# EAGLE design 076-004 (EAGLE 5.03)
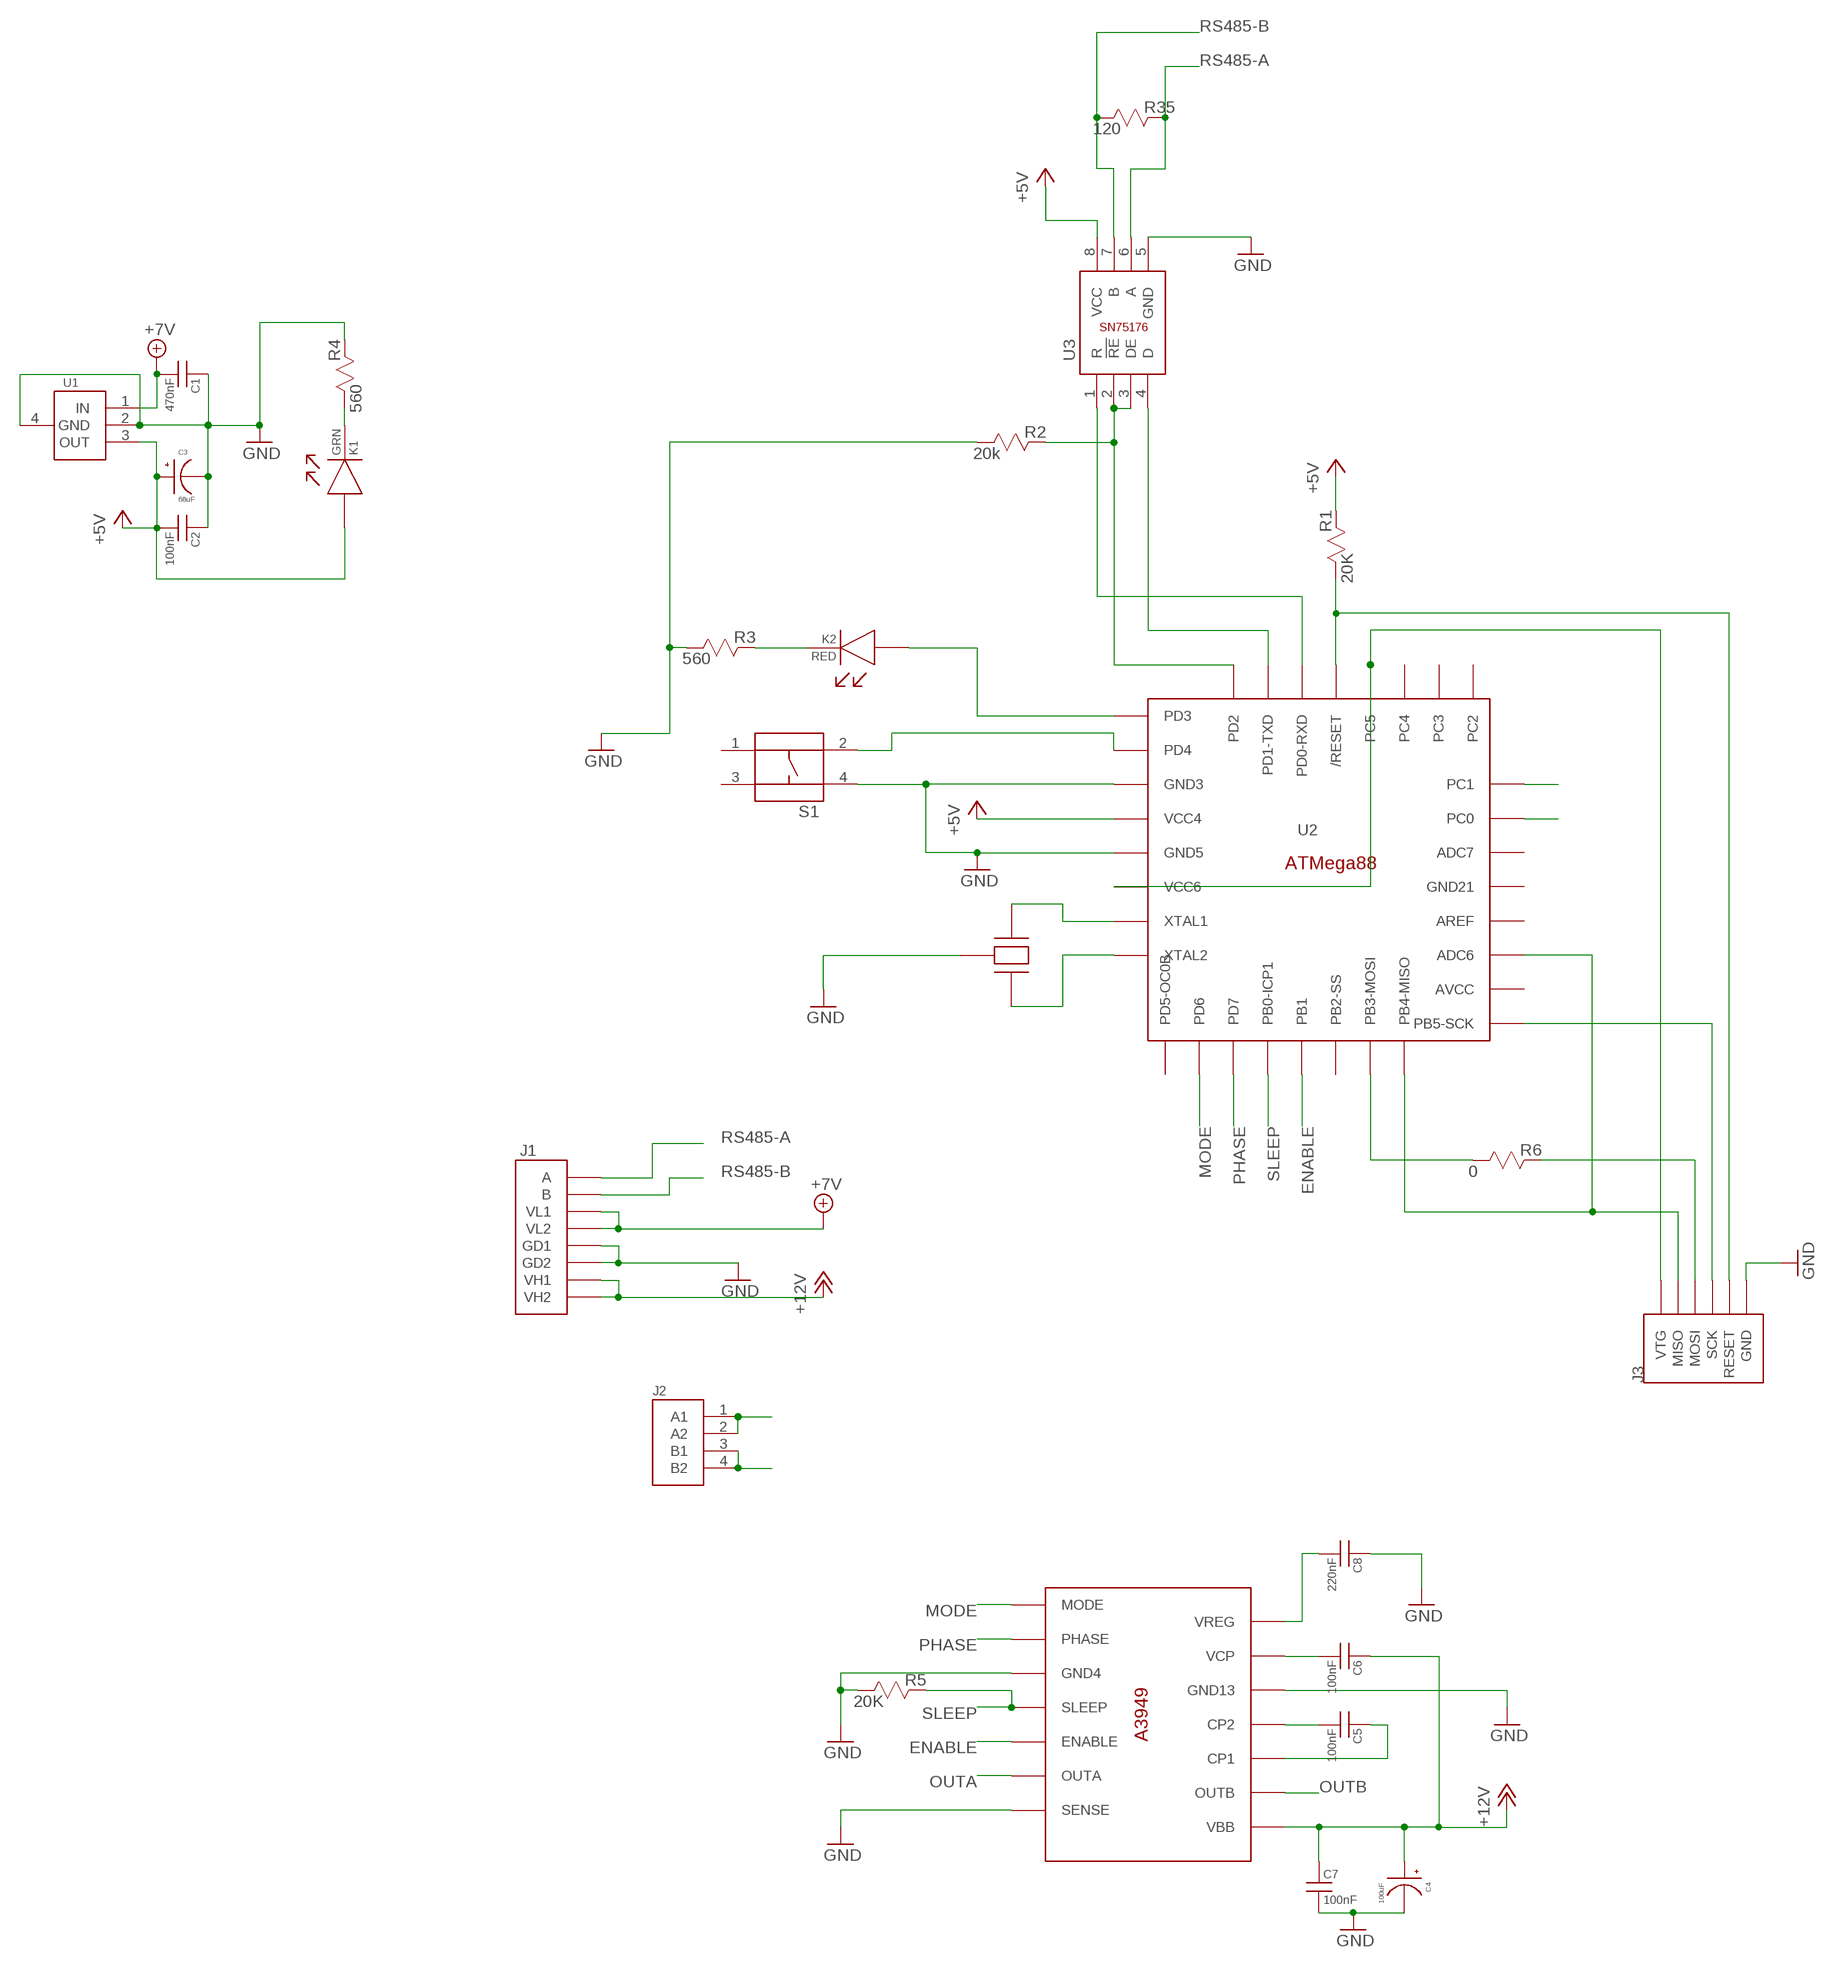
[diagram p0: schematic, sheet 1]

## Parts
C1  470nF  CAP_NONPOLARC1206  [C1206]
C2  100nF  CAP_NONPOLARC1206  [C1206]
C3  68uF  POLAR_CAPACITOR68UF  [ECAP-D8]
C4  100uF  POLAR_CAPACITOR100UF  [ECAP-F]
C5  100nF  CAP_NONPOLARC1206  [C1206]
C6  100nF  CAP_NONPOLARC1206  [C1206]
C7  100nF  CAP_NONPOLARC1206  [C1206]
C8  220nF  CAP_NONPOLARC1206  [C1206]
J1  IO_HEADER  [IO_HEADER]
J2  DC_MOTOR_HEADER  [2X2HEADER]
J3  ISP_HEADER  [ISP_HEADER]
K1  GRN  LED1206  [R1206]
K2  RED  LED1206  [R1206]
R1  20K  RESISTORR1206  [R1206]
R2  20k  RESISTORR1206  [R1206]
R3  560  RESISTORR1206  [R1206]
R4  560  RESISTORR1206  [R1206]
R5  20K  RESISTORR1206  [R1206]
R6  0  RESISTORR1206  [R1206]
R35  120  RESISTORR1206  [R1206]
S1  PUSHBUTTON-SMD  [PUSHBUTTON-SMD]
U1  5VREG  [SOT223]
U2  ATMEGA88PA  [TQFP32-08]
U3  SN75176A  [SO08]
U4  A3949  [SO-16DW]
X1  RESONATOR-SMD  [EFOBM]

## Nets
+5V: C2.2(M) C3.P K1.1(A) R1.2 U1.3(OUT) U2.4(VCC4) U3.8(VCC)
+7V: C1.2(M) J1.3(VL1) J1.4(VL2) U1.1(IN)
+12V: C4.P C6.1(P) C7.1(P) J1.7(VH1) J1.8(VH2) U4.9(VBB)
ENABLE: U2.13(PB1) U4.6(ENABLE)
GND: C1.1(P) C2.1(P) C3.N C4.N C7.2(M) C8.1(P) J1.5(GD1) J1.6(GD2) J3.4(GND) R2.1 R3.1 R4.2 R5.1 S1.4 U1.2(GND) U1.4(GND2) U2.3(GND3) U2.5(GND5) U3.5(GND) U4.4(GND4) U4.8(SENSE) U4.13(GND13) X1.2
MODE: U2.10(PD6) U4.2(MODE)
N$1: K1.2(C) R4.1
N$2: J3.3(RESET) R1.1 U2.29(/RESET)
N$3: U2.7(XTAL1) X1.1
N$4: U2.8(XTAL2) X1.3
N$5: J3.2(SCK) U2.17(PB5-SCK)
N$6: K2.2(C) R3.2
N$7: C8.2(M) U4.15(VREG)
N$8: C5.2(M) U4.12(CP2)
N$9: R2.2 U2.32(PD2) U3.2(!RE) U3.3(DE)
N$10: U2.30(PD0-RXD) U3.1(R)
N$11: U2.31(PD1-TXD) U3.4(D)
N$12: J3.6(VTG) U2.6(VCC6) U2.28(PC5)
N$13: S1.2 U2.2(PD4)
N$14: C5.1(P) U4.11(CP1)
N$15: J3.5(MOSI) R6.2
N$16: K2.1(A) U2.1(PD3)
N$17: C6.2(M) U4.14(VCP)
OUTA: J2.1(A1) J2.2(A2) U4.7(OUTA)
OUTB: J2.3(B1) J2.4(B2) U4.10(OUTB)
PHASE: U2.11(PD7) U4.3(PHASE)
RS485-A: J1.1(A) R35.2 U3.6(A)
RS485-B: J1.2(B) R35.1 U3.7(B)
SLEEP: R5.2 U2.12(PB0-ICP1) U4.5(SLEEP)
U1: J3.1(MISO) U2.16(PB4-MISO) U2.19(ADC6)
X_LED: U2.23(PC0)
Y_LED: U2.24(PC1)
Z_DIR: R6.1 U2.15(PB3-MOSI)
Unconnected: S1.1 S1.3 U2.9(PD5-OC0B) U2.14(PB2-SS) U2.18(AVCC) U2.20(AREF) U2.21(GND21) U2.22(ADC7) U2.25(PC2) U2.26(PC3) U2.27(PC4)

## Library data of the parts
C1 C2 C5-C8 = Routroller:CAP_NONPOLAR
C3 C4 = MtMM:POLAR_CAPACITOR
J1 = MtMM:IO_HEADER
J2 = MtMM:DC_MOTOR_HEADER
J3 = MtMM:ISP_HEADER
K1 K2 = MtMM:LED1206
R1-R6 R35 = Routroller:RESISTOR
S1 = MtMM:PUSHBUTTON-SMD
U1 = MtMM:5VREG
U2 = MtMM:ATMEGA88PA
U3 = Routroller:SN75176A
U4 = MtMM:A3949
X1 = im:RESONATOR-SMD

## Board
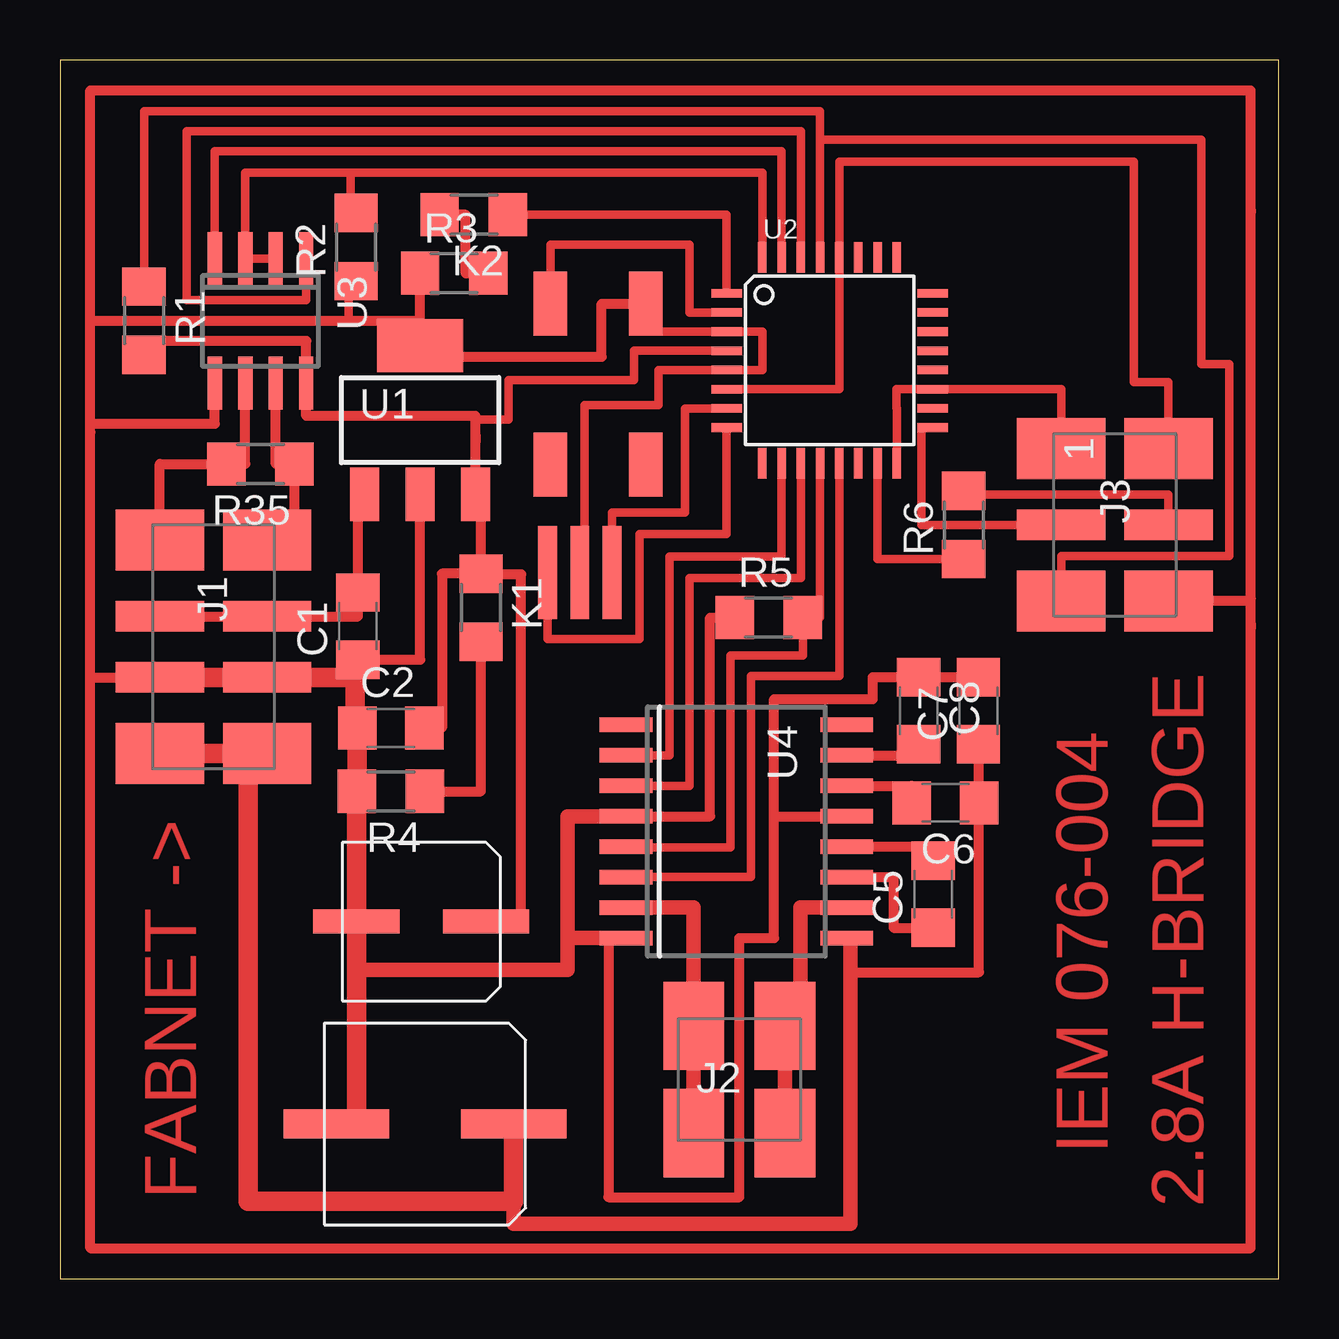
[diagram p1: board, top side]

Size 50.8 x 50.8 mm. Coordinates in mm from the lower left corner, seen from the top.
Outline: 0,0 50.8,0 50.8,50.8 0,50.8 0,0
Copper layers (1*16): Top 0.035mm / dielectric 1.5mm / Bottom 0.035mm
Design rules "default": minimum track width 10mil, minimum drill 24mil, track to track 8mil, track to pad 8mil, pad to pad 8mil, via to via 8mil, smd to smd 8mil, copper to edge 40mil, drill to drill 8mil, minimum pad ring 10mil, minimum via ring 8mil, stop-mask expansion 4mil, vias tented up to drill 0mil, thermal gap 10mil

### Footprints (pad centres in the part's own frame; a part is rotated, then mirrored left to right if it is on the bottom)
C1206 = smd 1.6 x 1.8: 1 -1.4,0; 2 1.4,0
ECAP-D8 = smd 3.6 x 1: N -2.7,0; P 2.7,0
ECAP-F = smd 4.4 x 1.2: N -3.7,0; P 3.7,0
IO_HEADER = smd 2.54 x 3.683: 1 -3.175,-2.235; 2 -3.175,2.235; 7 5.715,-2.235; 8 5.715,2.235 | smd 1.27 x 3.683: 3 0,-2.235; 4 0,2.235; 5 2.54,-2.235; 6 2.54,2.235
2X2HEADER = smd 2.54 x 3.683: 1 -1.905,-2.235; 2 -1.905,2.235; 3 1.905,-2.235; 4 1.905,2.235
ISP_HEADER = smd 2.54 x 3.683: 1 -3.175,-2.235; 3 3.175,-2.235; 4 3.175,2.235; 6 -3.175,2.235 | smd 1.27 x 3.683: 2 0,-2.235; 5 0,2.235
R1206 = smd 1.6 x 1.803: 1 -1.422,0; 2 1.422,0
PUSHBUTTON-SMD = smd 2.667 x 1.397: 1 3.353,-1.981; 2 -3.353,-1.981; 3 3.353,1.981; 4 -3.353,1.981
SOT223 = smd 1.219 x 2.235: 1 -2.311,-3.099; 2 0,-3.099; 3 2.311,-3.099 | smd 3.6 x 2.2: 4 0,3.099
TQFP32-08 = smd 1.27 x 0.356: 1 -4.293,2.8; 2 -4.293,2; 3 -4.293,1.2; 4 -4.293,0.4; 5 -4.293,-0.4; 6 -4.293,-1.2; 7 -4.293,-2; 8 -4.293,-2.8; 17 4.293,-2.8; 18 4.293,-2; 19 4.293,-1.2; 20 4.293,-0.4; 21 4.293,0.4; 22 4.293,1.2; 23 4.293,2; 24 4.293,2.8 | smd 0.356 x 1.27: 9 -2.8,-4.293; 10 -2,-4.293; 11 -1.2,-4.293; 12 -0.4,-4.293; 13 0.4,-4.293; 14 1.2,-4.293; 15 2,-4.293; 16 2.8,-4.293; 25 2.8,4.293; 26 2,4.293; 27 1.2,4.293; 28 0.4,4.293; 29 -0.4,4.293; 30 -1.2,4.293; 31 -2,4.293; 32 -2.8,4.293
SO08 = smd 0.6 x 2.2: 1 -1.905,-2.6; 2 -0.635,-2.6; 3 0.635,-2.6; 4 1.905,-2.6; 5 1.905,2.6; 6 0.635,2.6; 7 -0.635,2.6; 8 -1.905,2.6
SO-16DW = smd 0.6 x 2.2: 1 -4.445,-4.6; 2 -3.175,-4.6; 3 -1.905,-4.6; 4 -0.635,-4.6; 5 0.635,-4.6; 6 1.905,-4.6; 7 3.175,-4.6; 8 4.445,-4.6; 9 4.445,4.6; 10 3.175,4.6; 11 1.905,4.6; 12 0.635,4.6; 13 -0.635,4.6; 14 -1.905,4.6; 15 -3.175,4.6; 16 -4.445,4.6
EFOBM = smd 0.787 x 3.886: 1 -1.346,0; 2 0,0; 3 1.346,0

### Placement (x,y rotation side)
C1  12.42,27.2 90 top
C2  13.79,22.96 0 top
C3  15.06,14.88 0 top
C4  15.21,6.45 0 top
C5  36.4,16.03 90 top
C6  36.91,19.84 180 top
C7  38.28,23.67 90 top
C8  35.79,23.67 270 top
J1  6.4,27.61 270 top
J2  28.32,8.31 0 top
J3  43.97,31.42 270 top
K1  17.55,27.97 270 top
K2  17.25,44.35 180 top
R1  3.51,39.93 270 top
R2  12.34,43 90 top
R3  16.43,41.91 0 top
R4  13.79,20.32 180 top
R5  29.54,27.56 0 top
R6  37.67,31.42 90 top
R35  8.36,33.96 180 top
S1  22.43,37.29 270 top
U1  15.01,35.79 0 top
U2  32.08,38.28 0 top
U3  8.36,39.93 180 top
U4  28.19,18.64 270 top
X1  21.67,29.44 180 top

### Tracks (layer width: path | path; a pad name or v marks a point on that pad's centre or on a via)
+5V
  Top 0.356: U2.4 23.93,38.68 23.93,37.47 18.69,37.47 18.69,35.81 17.32,35.81
  Top 0.406: R1.2 3.5,39.09 10.26,39.09 U3.8 10.26,35.97 17.32,35.97 17.32,35.81 17.32,35.18 | 17.32,35.18 U1.3 17.55,32.69 K1.1 | 17.32,35.18 17.32,34.85 | C2.2 15.93,22.96 15.93,29.39 K1.1 | C3.P 19.23,14.88 19.23,29.36 17.55,29.36 K1.1
+7V
  Top 0.406: J1.3 J1.4 12.42,27.61 C1.2 12.42,32.69 U1.1
+12V
  Top 0.406: C7.1 38.31,22.27 C6.1 38.31,12.78 32.94,12.78
  Top 0.61: U4.9 32.94,14.2 32.94,12.78 32.94,2.29 18.91,2.29 18.91,3.23
  Top 0.813: 8.08,21.89 J1.7 | 8.08,21.89 J1.8 | C4.P 18.91,3.23 7.85,3.23 7.85,21.89 8.08,21.89
ENABLE
  Top 0.356: U2.13 32.48,25.12 28.8,25.12 28.8,16.74 U4.6
GND
  Top 0.356: R2.1 12.04,41.58 12.04,39.93 | S1.4 24.41,39.48 U2.3 29.29,39.48 29.29,37.88 U2.5 24.94,37.88 24.94,36.42 21.87,36.42 21.87,30.1 21.67,30.1 X1.2
  Top 0.406: U3.5 6.45,35.64 1.27,35.64 1.27,35.28 | 49.63,27.33 49.63,1.27 1.27,1.27 1.27,25.07 | 49.63,27.33 49.63,28.37 | 49.63,28.37 49.63,44.58 | 49.63,44.58 49.63,49.53 1.27,49.53 1.27,40.01 | 1.27,35.28 1.27,40.01 | 49.63,44.58 49.63,44.42 | 49.63,27.33 49.63,27.08 | 1.27,40.01 1.27,39.93 12.04,39.93 15.01,39.93 | 1.27,25.07 J1.5 | 1.27,25.07 1.27,35.28 | 15.01,39.93 U1.4 15.01,38.43 22.58,38.43 22.58,40.64 S1.4 | 12.29,25.07 12.42,25.07 C1.1 15.01,25.8 U1.2 15.04,32.69 | 12.39,20.32 R4.2 | 12.29,22.96 C2.1 | C3.N | 15.01,39.93 R3.1 | U4.4 27.1,19.28 27.1,27.56 R5.1 | 29.77,19.28 U4.13 | 29.77,19.28 29.77,14.2 28.32,14.2 28.32,3.4 22.86,3.4 22.86,14.2 23.04,14.2 | C7.2 C8.1 33.88,25.07 33.88,24.16 29.77,24.16 29.77,19.28 | J3.4 49.51,28.25 arc90 49.63,28.37
  Top 0.61: U4.4 21.16,19.28 21.16,14.2 | 21.16,14.2 23.04,14.2 U4.8 | 21.16,14.2 21.16,12.88 12.36,12.88
  Top 0.813: J1.5 J1.6 12.29,25.07 12.29,22.96 | C2.1 12.39,20.32 | R4.2 C3.N | C4.N 12.36,6.45 12.36,12.88 C3.N
MODE
  Top 0.356: U2.10 30.08,30.1 25.4,30.1 25.4,21.82 U4.2
N$1
  Top 0.406: R4.1 17.55,20.32 K1.2
N$2
  Top 0.356: R1.1 3.5,48.67 31.68,48.67 U2.29 31.68,47.47 47.57,47.47 47.57,38.12 48.74,38.12 48.74,30.12 41.73,30.12 J3.3
N$3
  Top 0.356: U2.7 26.06,36.28 26.06,31.93 23.01,31.93 X1.1
N$4
  Top 0.356: 27.36,35.48 U2.8 27.79,31.04 24.16,31.04 24.16,26.67 20.32,26.67 X1.3
N$5
  Top 0.356: U2.17 35.92,35.48 35.92,31.42 J3.2
N$6
  Top 0.406: R3.2 16.92,41.91 16.92,44.35 K2.2
N$7
  Top 0.406: U4.15 35.79,21.82 C8.2
N$8
  Top 0.406: U4.12 36.4,18.01 C5.2
N$9
  Top 0.356: U2.32 29.28,46.1 13.44,46.1 | 12.12,46.1 7.72,46.1 U3.3 U3.2 | 12.12,46.1 13.44,46.1 | 13.44,46.1 13.49,46.1 | R2.2 12.12,44.42 12.12,46.1
N$10
  Top 0.356: U2.30 30.88,47.83 5.28,47.83 5.28,40.79 10.26,40.79 U3.1
N$11
  Top 0.356: U2.31 30.08,46.99 6.45,46.99 U3.4
N$12
  Top 0.356: J3.6 46.2,37.36 44.76,37.36 44.76,46.56 32.48,46.56 U2.28 32.48,37.08 29.46,37.08 arc-90 29.46,37.08 U2.6
N$13
  Top 0.356: U2.2 26.24,40.28 26.24,43.1 20.45,43.1 S1.2
N$14
  Top 0.406: U4.11 34.75,16.74 34.75,14.63 C5.1
N$15
  Top 0.356: J3.5 46.2,32.69 38.33,32.69 38.33,32.84 R6.2
N$16
  Top 0.356: U2.1 27.79,44.35 K2.1
N$17
  Top 0.406: U4.14 35.51,20.55 C6.2
OUTA
  Top 0.61: U4.7 26.42,15.47 J2.2 J2.1
OUTB
  Top 0.61: J2.3 J2.4 30.86,10.54 30.86,15.47 U4.10
PHASE
  Top 0.356: U2.11 30.88,29.21 26.24,29.21 26.24,20.55 U4.3
RS485-A
  Top 0.406: U3.6 7.72,33.96 R35.2 4.17,33.96 J1.1
RS485-B
  Top 0.406: U3.7 8.99,33.96 R35.1 9.78,30.79 J1.2
SLEEP
  Top 0.356: U2.12 31.68,27.56 R5.2 30.96,25.98 27.94,25.98 27.94,17.98 23.59,17.98 U4.5
U1
  Top 0.356: U2.16 34.88,36.3 34.87,36.3 34.87,37.08 U2.19 41.73,37.08 J3.1
Z_DIR
  Top 0.356: U2.15 34.08,30 R6.1

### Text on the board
Top: IEM 076-004 | FABNET -> | 2.8A H-BRIDGE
